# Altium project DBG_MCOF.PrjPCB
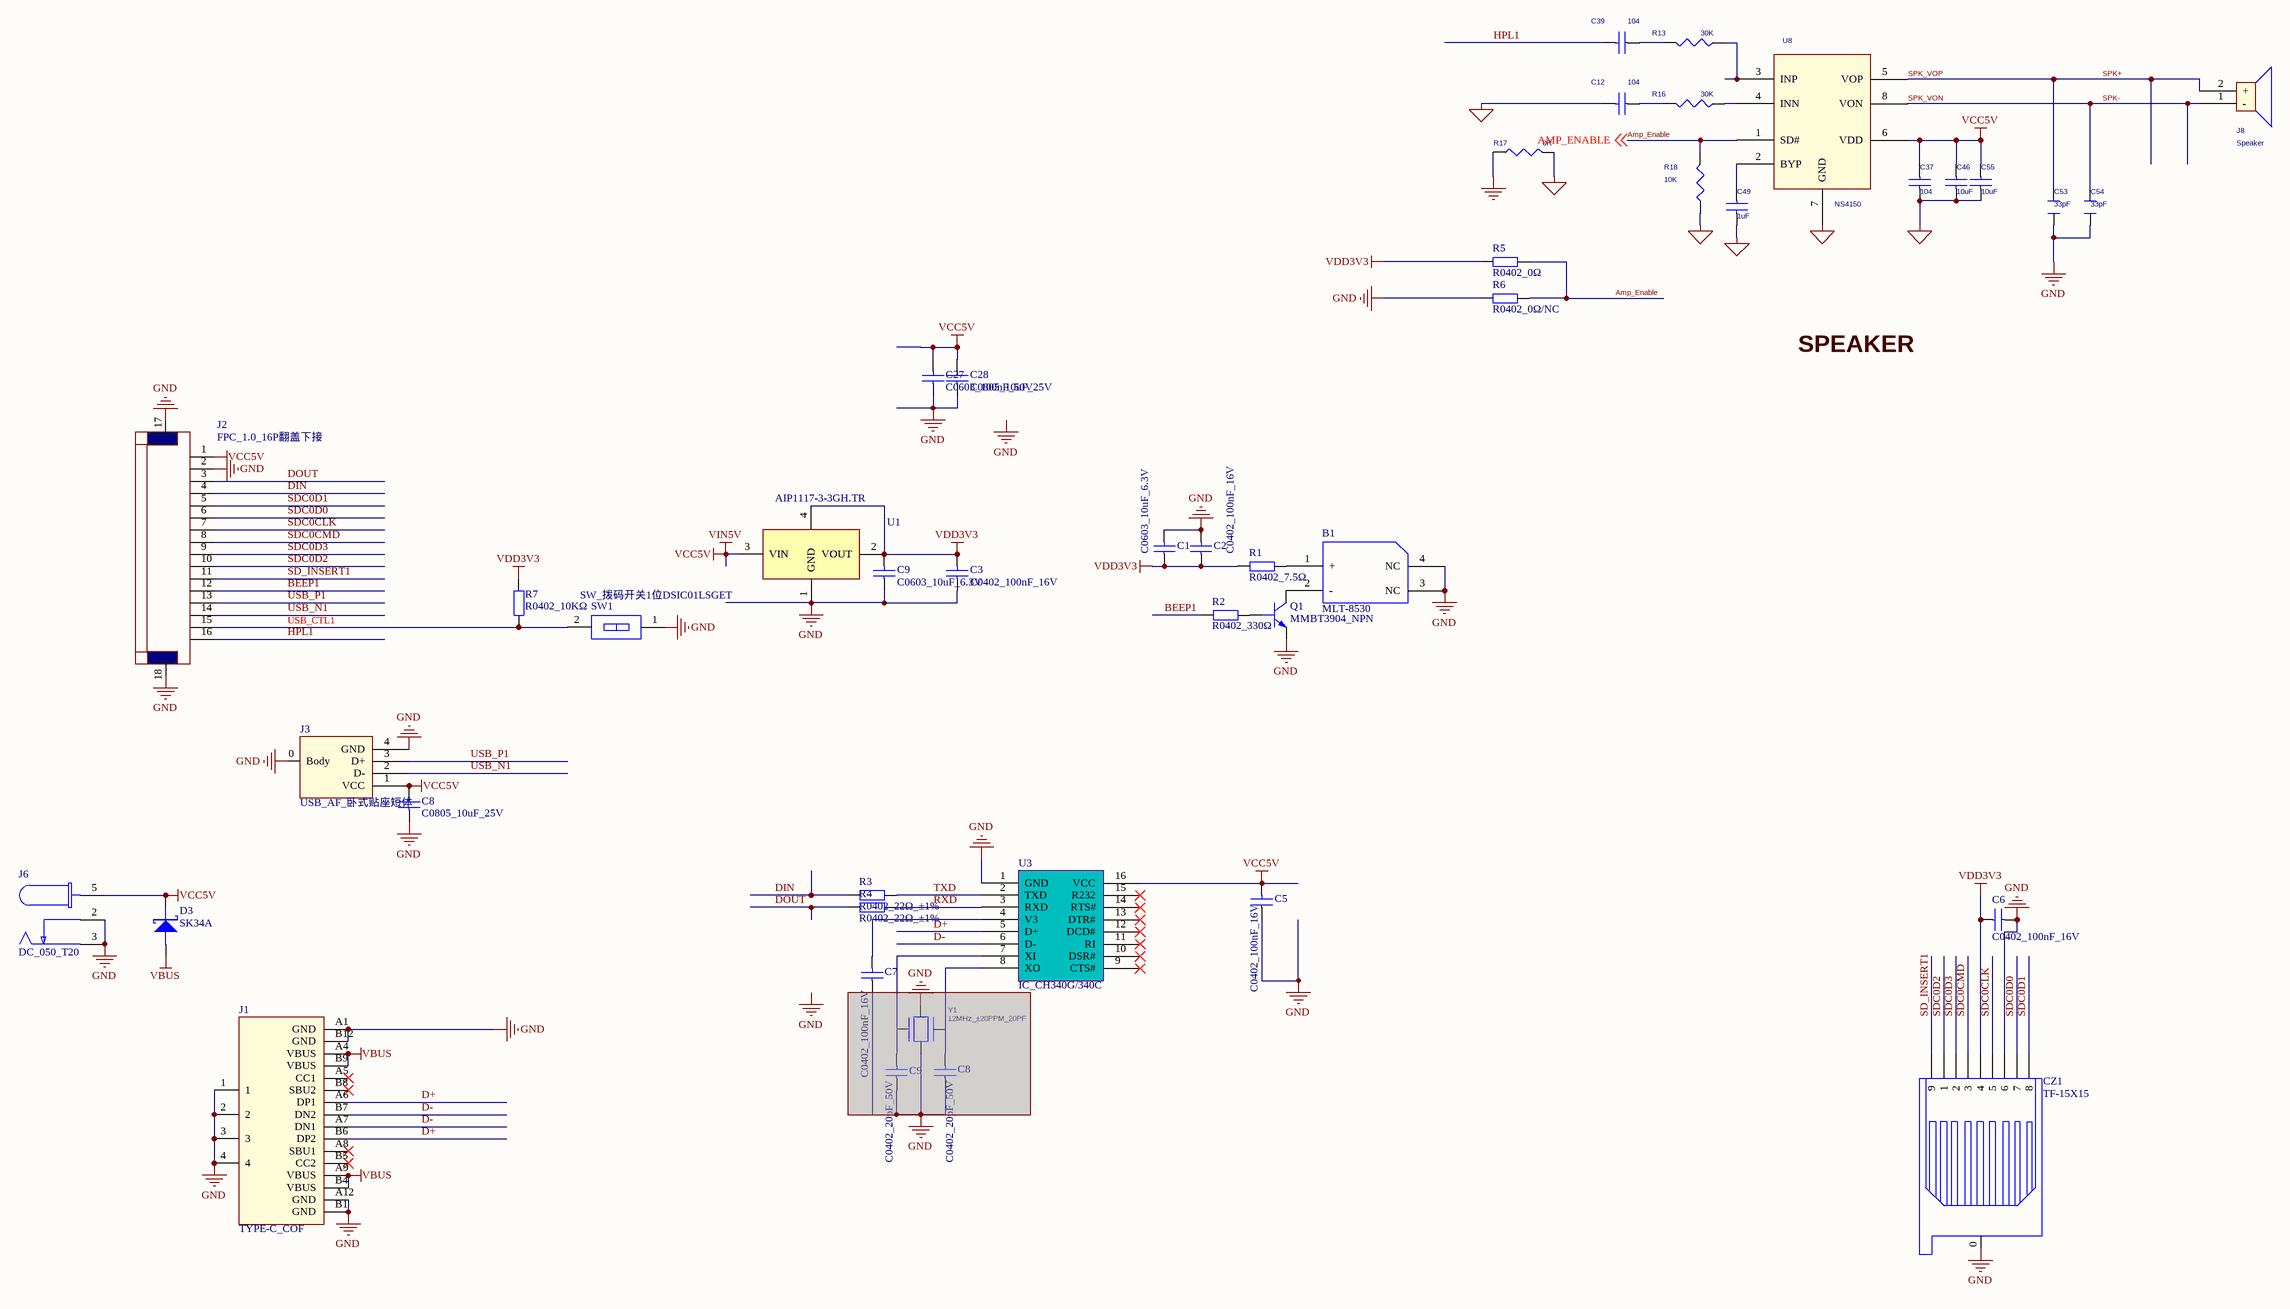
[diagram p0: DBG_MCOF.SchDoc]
1 sheet, 45 parts. Net scope: global (net labels, ports and power ports of the same name join across sheets).
Board file: DBG_MCOF.PcbDoc

## Sheet DBG_MCOF.SchDoc
size A2

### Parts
(Parts that share a designator on the sheet are numbered #1, #2 ... from top to bottom, then left to right.)
B1  MLT-8530  [BUZZER-SMD]
C1  C0603_10uF_6.3V  [0603C]
C2  C0402_100nF_16V  [0402C]
C3  C0402_100nF_16V  [0402C]
C5  C0402_100nF_16V  [0402C]
C6  C0402_100nF_16V  [0402C]
C7  C0402_100nF_16V  [0402C]
C8#1  C0805_10uF_25V  [0805C]
C8#2  C0402_20pF_50V  [0402C]  (masked out: inside a compile mask, not in the netlist)
C9#1  C0603_10uF_6.3V  [0603C]
C9#2  C0402_20pF_50V  [0402C]  (masked out: inside a compile mask, not in the netlist)
C12  104  [0402C]
C27  C0603_100nF_50V  [0603C]
C28  C0805_10uF_25V  [0805C]
C37  104  [0402C]
C39  104  [0402C]
C46  10uF  [0603C]
C49  1uF  [0402C]
C53  33pF  [0402C]
C54  33pF  [0402C]
C55  10uF  [0603C]
CZ1  TF-15X15  [T-F]
D3  SK34A  [DO-214AC]
J1  TYPE-C_COF  [TYPE-C_COF]
J2  FPC_1.0_16P翻盖下接  [FFC-16S-1.0]
J3  USB_AF_卧式贴座短体  [USB-102SD]
J6  DC_050_T20  [DC_055_2.5]
J8  Speaker  [PH-2.0-2P]
Q1  MMBT3904_NPN  [SOT-23]
R1  R0402_7.5Ω  [0402R]
R2  R0402_330Ω  [0402R]
R3  R0402_22Ω_±1%  [0402R]
R4  R0402_22Ω_±1%  [0402R]
R5  R0402_0Ω  [0402R]
R6  R0402_0Ω/NC  [0402R]
R7  R0402_10KΩ  [0402R]
R13  30K  [0402R]
R16  30K  [0402R]
R17  0R  [0603R]
R18  10K  [0402R]
SW1  SW_拨码开关1位DSIC01LSGET  [SW1]
U1  AIP1117-3-3GH.TR  [SOT89]
U3  IC_CH340G/340C  [SOIC-16]
U8  NS4150  [MSOP-8]
Y1  12MHz_±20PPM_20PF  [NX3225DA]  (masked out: inside a compile mask, not in the netlist)

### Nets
GND: B1.3(NC) B1.4(NC) C1.1 C2.1 C3.2 C5.2 C6.1 C8#1.2 C9#1.2 C27.2 C28.2 C53.1 C54.1 CZ1.0 CZ1.6 J1.1 J1.2 J1.3 J1.4 J1.A1(GND) J1.A12(GND) J1.B1(GND) J1.B12(GND) J2.2 J2.17 J2.18 J3.0(Body) J3.4(GND) J6.2 J6.3 Q1.2(E) R6.2 R17.1 SW1.1 U1.1(GND) U3.1(GND)
GND_ADDA: C12.2 C37.2 C46.2 C49.2 C55.2 R17.2 R18.1 U8.7(GND)
VBUS: D3.1 J1.A4(VBUS) J1.A9(VBUS) J1.B4(VBUS) J1.B9(VBUS)
VCC5V: C5.1 C8#1.1 C27.1 C28.1 C37.1 C46.1 C55.1 D3.2 J2.1 J3.1(VCC) J6.5 U1.3(VIN) U3.16(VCC) U8.6(VDD)  [also labelled VIN5V]
VDD3V3: C1.2 C2.2 C3.1 C6.2 C9#1.1 CZ1.4 R1.1 R5.2 R7.2 U1.2(VOUT) U1.4
Amp_Enable: R5.1 R6.1 R18.2 U8.1(SD#) ; off-sheet AMP_ENABLE
BEEP1: J2.12 R2.1
D+: J1.A6(DP1) J1.B6(DP2) U3.5(D+)
D-: J1.A7(DN1) J1.B7(DN2) U3.6(D-)
DIN: J2.4 R3.1
DOUT: J2.3 R4.1
HPL1: C39.2 J2.16
RXD: R4.2 U3.3(RXD)
SD_INSERT1: CZ1.9 J2.11
SDC0CLK: CZ1.5 J2.7
SDC0CMD: CZ1.3 J2.8
SDC0D0: CZ1.7 J2.6
SDC0D1: CZ1.8 J2.5
SDC0D2: CZ1.1 J2.10
SDC0D3: CZ1.2 J2.9
SPK+: C53.2 J8.2(+) U8.5(VOP)  [also labelled SPK_VOP]
SPK-: C54.2 J8.1(-) U8.8(VON)  [also labelled SPK_VON]
TXD: R3.2 U3.2(TXD)
USB_CTL1: J2.15 R7.1 SW1.2
USB_N1: J2.14 J3.2(D-)
USB_P1: J2.13 J3.3(D+)
NetB1_1: B1.1(+) R1.2
NetB1_2: B1.2(-) Q1.3(C)
NetC7_1: C7.1 U3.4(V3)
NetC12_1: C12.1 R16.2
NetC39_1: C39.1 R13.2
NetC49_1: C49.1 U8.2(BYP)
NetQ1_1: Q1.1(B) R2.2
NetR13_1: R13.1 U8.3(INP)
NetR16_1: R16.1 U8.4(INN)

Not connected (* = marked no-connect by the designer): C7 2; J1 A5(CC1)* A8(SBU1)* B5(CC2)* B8(SBU2)*; U3 7(XI) 8(XO) 9(CTS#)* 10(DSR#)* 11(RI)* 12(DCD#)* 13(DTR#)* 14(RTS#)* 15(R232)*

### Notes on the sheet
- SPEAKER
- Labels drawn without touching a wire or pin: GND

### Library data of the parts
B1 = BUZZER_MLT-8530: 1.09.02.0001
C1 C9#1 = C0603_10uF_6.3V: 1.02.02.0030
C2 C3 = C0402_100nF_16V: 1.02.01.0026
C5-C7 = C0402_100nF_16V: 1.19.01.0004
C8#1 = C0805_10uF_25V: 1.02.03.0017
C8#2 C9#2 = C0402_20pF_50V: 1.19.01.0015
C12 C39 = CAP NP_Dup1
C27 = C0603_100nF_50V: 1.02.01.0009
C28 = C0805_10uF_25V: 1.02.02.0009
C37 C46 C49 C55 = CAP NP_Dup2
C53 C54 = CAPACITOR_0_Dup1: PAGE: 2
CZ1 = TF-15X15: 1.07.01.0027
D3 = D_SK34A: 1.05.02.0005
J1 = TYPE-C_COF: 99
J2 = FPC_1.0_16P翻盖下接: 99
J3 = USB_AF_卧式贴座短体: 1.08.02.0008
J6 = DC_050_T20: 1.08.02.0088
J8 = SPEAKER_1
Q1 = Q_MMBT3904_NPN: 1.05.04.0004
R1 = R0402_7.5Ω: 1.01.01.0011
R2 = R0402_330Ω: 1.01.01.0022
R3 R4 = R0402_22Ω_±1%: 1.01.05.0002
R5 R6 = R0402_0Ω: 1.01.01.0001
R7 = R0402_10KΩ: 1.01.01.0045
R13 R16-R18 = R_Dup2
SW1 = SW_拨码开关1位DSIC01LSGET: 1.09.04.0011
U1 = IC_SPX1117M3-L-3-3/TR: 1.07.02.0004
U8 = LPA2010
Y1 = XTAL_12MHz_±20PPM_20PF: 1.05.01.0005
